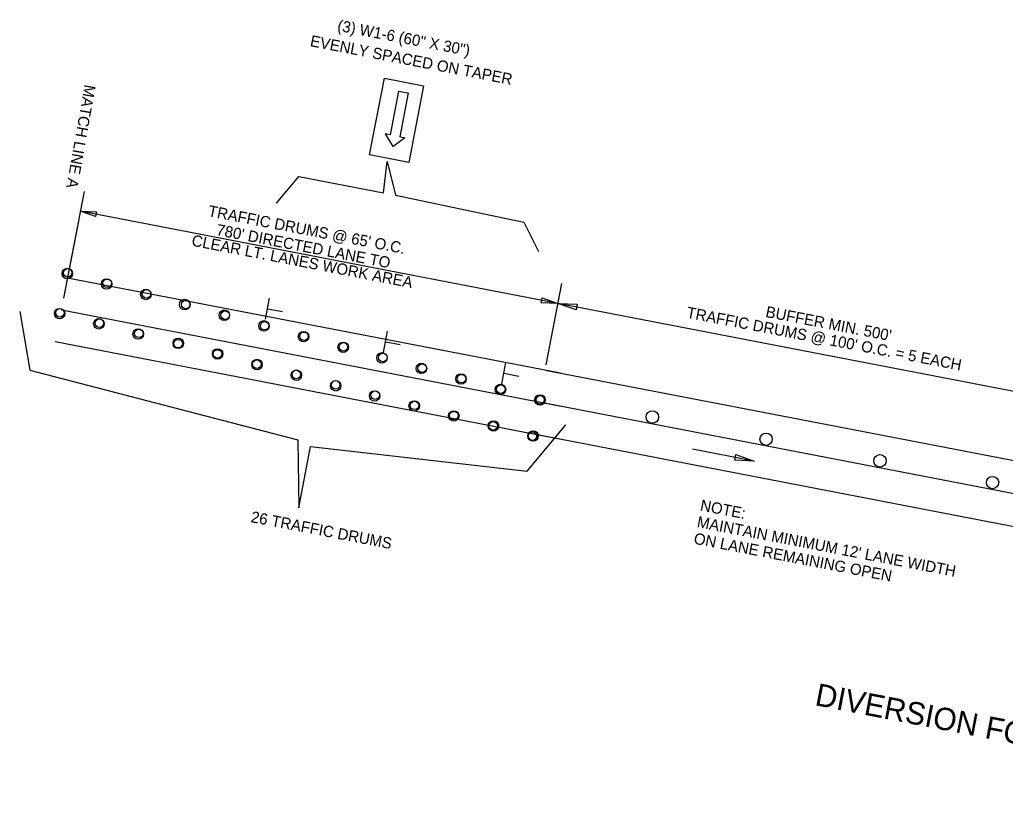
# Model space of a CAD drawing. Extents: x 606969 to 609391, y 416008 to 419486.
# Drawn here: x 606976.6 to 607029.4, y 419395.6 to 419438.1 of the extents above; entities that cross this region are included whole.
import ezdxf

# ---------------------------------------------------------------- set-up
doc = ezdxf.new("R2010")
doc.units = 0
doc.layers.add('Default', color=7, linetype='Continuous')

msp = doc.modelspace()

# ---------------------------------------------------------------- linework, layer by layer
at = {"layer": 'Default'}
for p, q in [((606996.865, 419434.266), (606996.412, 419431.919)), ((606996.865, 419434.266), (606997.388, 419434.165)), ((606997.388, 419434.165), (606996.935, 419431.818)), ((606996.412, 419431.919), (606996.151, 419431.97)), ((606996.151, 419431.97), (606996.563, 419431.295)), ((606996.563, 419431.295), (606997.196, 419431.768)), ((606996.935, 419431.818), (606997.196, 419431.768)), ((606980.019, 419428.88), (606978.914, 419423.157)), ((607005.4, 419422.882), (606979.795, 419427.825)), ((606979.795, 419427.825), (606980.674, 419427.788)), ((606980.624, 419427.532), (606979.795, 419427.825)), ((606980.674, 419427.788), (606980.624, 419427.532)), ((606979.73, 419427.385), (606978.914, 419423.157)), ((606979.125, 419424.25), (607005.542, 419419.15)), ((607005.605, 419423.941), (607004.765, 419419.593)), ((606989.736, 419422.028), (606989.956, 419423.168)), ((607004.522, 419422.919), (607004.571, 419423.175)), ((607005.4, 419422.882), (607004.522, 419422.919)), ((607004.571, 419423.175), (607005.4, 419422.882)), ((607035.75, 419417.024), (607005.4, 419422.882)), ((607005.4, 419422.882), (607006.441, 419422.839)), ((607006.383, 419422.535), (607005.4, 419422.882)), ((607006.441, 419422.839), (607006.383, 419422.535)), ((606978.795, 419422.543), (607005.582, 419417.372)), ((606989.862, 419422.592), (606990.641, 419422.442)), ((606996.056, 419420.256), (606996.276, 419421.397)), ((606978.466, 419420.836), (607005.589, 419415.6)), ((606996.182, 419420.82), (606996.961, 419420.67)), ((607002.408, 419418.571), (607002.628, 419419.711)), ((607002.534, 419419.135), (607003.313, 419418.985)), ((607004.73, 419419.307), (607031.136, 419414.21)), ((607004.312, 419417.617), (607031.02, 419412.462)), ((607004.03, 419415.901), (607031.038, 419410.688)), ((607015.937, 419414.423), (607012.619, 419415.064)), ((607014.896, 419414.467), (607014.954, 419414.77)), ((607015.937, 419414.423), (607014.896, 419414.467)), ((607014.954, 419414.77), (607015.937, 419414.423))]:
    msp.add_line(p, q, dxfattribs=at)
msp.add_lwpolyline([(606995.312, 419430.841), (606996.107, 419434.957), (606998.211, 419434.55), (606997.417, 419430.435)], close=True, dxfattribs=at)
for points in [[(606990.322, 419428.254), (606991.516, 419429.684), (606996.055, 419428.808), (606996.257, 419430.489), (606996.703, 419428.683), (607003.579, 419427.237), (607004.375, 419425.66)], [(606976.558, 419422.454), (606977.098, 419419.303), (606991.46, 419415.565), (606991.52, 419411.913), (606992.156, 419415.208), (607003.765, 419413.887), (607005.828, 419416.374)]]:
    msp.add_lwpolyline(points, dxfattribs=at)
for centre, radius in [((606979.11, 419424.482), 0.281), ((606979.119, 419424.527), 0.229), ((606979.131, 419424.524), 0.229), ((606981.215, 419423.921), 0.281), ((606981.242, 419423.956), 0.229), ((606983.32, 419423.359), 0.281), ((606983.353, 419423.388), 0.229), ((606985.403, 419422.818), 0.281), ((606985.465, 419422.82), 0.229), ((606978.695, 419422.333), 0.281), ((606978.704, 419422.377), 0.229), ((606978.716, 419422.374), 0.229), ((606987.527, 419422.246), 0.281), ((606987.576, 419422.252), 0.229), ((606980.803, 419421.785), 0.281), ((606980.828, 419421.823), 0.229), ((606989.651, 419421.673), 0.281), ((606989.687, 419421.684), 0.229), ((606982.91, 419421.237), 0.281), ((606982.939, 419421.272), 0.229), ((606991.775, 419421.101), 0.281), ((606991.798, 419421.116), 0.229), ((606985.058, 419420.74), 0.281), ((606985.051, 419420.721), 0.229), ((606993.899, 419420.529), 0.281), ((606993.91, 419420.548), 0.229), ((606987.169, 419420.17), 0.281), ((606987.162, 419420.169), 0.229), ((606995.978, 419419.96), 0.281), ((606996.021, 419419.98), 0.229), ((606989.279, 419419.601), 0.281), ((606989.274, 419419.618), 0.229), ((606998.096, 419419.395), 0.281), ((606998.132, 419419.412), 0.229), ((606991.39, 419419.031), 0.281), ((606991.386, 419419.067), 0.229), ((607000.215, 419418.831), 0.281), ((607000.244, 419418.844), 0.229), ((606993.5, 419418.462), 0.281), ((606993.497, 419418.516), 0.229), ((607002.333, 419418.267), 0.281), ((606995.584, 419417.919), 0.281), ((606995.609, 419417.965), 0.229), ((607002.355, 419418.276), 0.229), ((606997.707, 419417.382), 0.281), ((606997.72, 419417.413), 0.229), ((607004.452, 419417.703), 0.281), ((607004.454, 419417.711), 0.229), ((607004.466, 419417.708), 0.229), ((606999.831, 419416.846), 0.281), ((606999.832, 419416.862), 0.229), ((607010.473, 419416.788), 0.333), ((607001.955, 419416.309), 0.281), ((607001.944, 419416.311), 0.229), ((607004.079, 419415.772), 0.281), ((607004.043, 419415.763), 0.229), ((607004.055, 419415.76), 0.229), ((607016.571, 419415.596), 0.333), ((607022.676, 419414.438), 0.333), ((607028.713, 419413.274), 0.333)]:
    msp.add_circle(centre, radius, dxfattribs=at)

# ---------------------------------------------------------------- texts
for s, height, rotation, p in [('(3) W1-6 (60" X 30")', 0.6, 349.0821, (606993.554, 419437.507)), ('EVENLY SPACED ON TAPER', 0.6, 349.0821, (606992.092, 419436.677)), ('MATCH LINE A', 0.6, 259.8804, (606980.042, 419434.641)), ("TRAFFIC DRUMS @ 65' O.C.", 0.6, 349.0745, (606986.62, 419427.561)), ("780' DIRECTED LANE TO", 0.6, 349.0745, (606987.065, 419426.551)), ('CLEAR LT. LANES WORK AREA', 0.6, 349.0745, (606985.741, 419425.979)), ("TRAFFIC DRUMS @ 100' O.C. = 5 EACH", 0.6, 349.0745, (607012.272, 419422.116)), ("BUFFER MIN. 500'", 0.6, 349.0745, (607016.511, 419422.156)), ('NOTE:', 0.6, 349.0745, (607013.003, 419411.78)), ('26 TRAFFIC DRUMS', 0.6, 349.0745, (606988.916, 419411.158)), ("MAINTAIN MINIMUM 12' LANE WIDTH", 0.6, 349.0745, (607012.831, 419410.891)), ('ON LANE REMAINING OPEN', 0.6, 349.0745, (607012.66, 419410.003)), ('DIVERSION FOR LT. LANE WORK ZONE', 1.2, 349.0745, (607019.141, 419401.344))]:
    msp.add_text(s, height=height, rotation=rotation, dxfattribs=at).set_placement(p)

doc.saveas('drawing.dxf')
